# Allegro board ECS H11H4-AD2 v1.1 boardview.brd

Outline 200 x 243.84 mm; copper layers: TOP, PWR, GND, BOTTOM. Coordinates in mm from the lower left corner of the outline.
Outline path: 0,239.78 0,4.06 0,4.06 arc(1.19,1.19) 4.06,0 4.06,0 195.94,0 195.94,0 arc(198.81,1.19) 200,4.06 200,4.06 200,239.78 200,239.78 arc(198.81,242.65) 195.94,243.84 195.94,243.84 4.06,243.84 4.06,243.84 arc(1.19,242.65) 0,239.78 0,239.78

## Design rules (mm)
net group DIFFPAIR135: nets M_CLK_A_N1 M_CLK_A_P1
net group DIFFPAIR136: nets M_CLK_A_N0 M_CLK_A_P0
net group DIFFPAIR337: nets USB3_TX_N3 USB3_TX_P3
net group DIFFPAIR338: nets USB3_RX_N3_R USB3_RX_P3_R
net group DIFFPAIR339: nets USB3_TX_N3_R USB3_TX_P3_R
net group DIFFPAIR351: nets CPU_BCLK_N CPU_BCLK_P
net group DIFFPAIR353: nets CPU_24MCLK_N CPU_24MCLK_P
net group DIFFPAIR355: nets PEX1_RX_N5 PEX1_RX_P5
net group DIFFPAIR356: nets HSODN5 HSODP5
net group DIFFPAIR357: nets PEX1_TX_N5 PEX1_TX_P5
net group DIFFPAIR358: nets GLAN_CLKN GLAN_CLKP
net group DIFFPAIR359: nets GLAN_TX_C_N6 GLAN_TX_C_P6
net group DIFFPAIR360: nets GLAN_TX_N6 GLAN_TX_P6
net group DIFFPAIR361: nets GLAN_RX_C_N6 GLAN_RX_C_P6
net group DIFFPAIR362: nets GLAN_RX_N6 GLAN_RX_P6
net group DIFFPAIR363: nets PEX1_TX_N8 PEX1_TX_P8
net group DIFFPAIR366: nets PEX1_RX_N8 PEX1_RX_P8
net group DIFFPAIR380: nets USB10+ USB10-
net group DIFFPAIR381: nets USB_H1 USB_L1
net group DIFFPAIR382: nets USB_H2 USB_L2
net group DIFFPAIR419: nets USB3_TX_N3_C USB3_TX_P3_C
net group DIFFPAIR420: nets USB_N3_R USB_P3_R
net group DIFFPAIR421: nets USB_N4_R USB_P4_R
net group DIFFPAIR422: nets USB+7 USB-7
net group DIFFPAIR423: nets SSD_100M_N SSD_100M_P
net group DIFFPAIR429: nets SATA_PCIE_TXN_S SATA_PCIE_TXP_S
net group DIFFPAIR430: nets SATA_PCIE_RXN_S SATA_PCIE_RXP_S
net group DIFFPAIR436: nets VCORE_GSENS VCORE_SENS
net group DIFFPAIR439: nets VCORE_GT_GSENS VCORE_GT_SENS
net group DIFFPAIR448: nets USB3_TX_N2_C USB3_TX_P2_C
net group DIFFPAIR449: nets MPEX1_TX_N10 MPEX1_TX_P10
net group DIFFPAIR450: nets M_PEX1_TX_N10 M_PEX1_TX_P10
net group DIFFPAIR451: nets M_PEX1_RX_N10 M_PEX1_RX_P10
net group DIFFPAIR452: nets USB_N3 USB_P3
net group DIFFPAIR453: nets USB_N4 USB_P4
net group DIFFPAIR454: nets N24049344 VSUMA-
net group DIFFPAIR455: nets N24049550 VSUMB-
net group DIFFPAIR456: nets PEX1_TX_N7_S PEX1_TX_P7_S
net group DIFFPAIR457: nets PEX1_RX_N7_S PEX1_RX_P7_S
net group PCH-CLK: nets PEX16_100M_N PEX16_100M_P
net group VRD: nets VRD_THERMDA VRD_THERMDC
net group DDR_DQS_A: nets M_DQS_A_N0 M_DQS_A_N1 M_DQS_A_N2 M_DQS_A_N3 M_DQS_A_N4 M_DQS_A_N5 M_DQS_A_N6 M_DQS_A_N7 M_DQS_A_P0 M_DQS_A_P1 M_DQS_A_P2 M_DQS_A_P3 M_DQS_A_P4 M_DQS_A_P5 M_DQS_A_P6 M_DQS_A_P7
net group DDR_DQS_B: nets M_DQS_B_N0 M_DQS_B_N1 M_DQS_B_N2 M_DQS_B_N3 M_DQS_B_N4 M_DQS_B_N5 M_DQS_B_N6 M_DQS_B_N7 M_DQS_B_P0 M_DQS_B_P1 M_DQS_B_P2 M_DQS_B_P3 M_DQS_B_P4 M_DQS_B_P5 M_DQS_B_P6 M_DQS_B_P7
net group DDRCLK-B: nets M_CLK_B_N0 M_CLK_B_N1 M_CLK_B_P0 M_CLK_B_P1
net group DDRCMD-A: nets M_BS_A0 M_BS_A1 M_BS_A2 M_CAS_A_L M_MA_A0 M_MA_A1 M_MA_A2 M_MA_A3 M_MA_A4 M_MA_A5 M_MA_A6 M_MA_A7 M_MA_A8 M_MA_A9 M_MA_A10 M_MA_A11 M_MA_A12 M_MA_A13 M_MA_A14 M_MA_A15 M_RAS_A_L M_WE_A_L
net group DDRCMD-B: nets M_BS_B0 M_BS_B1 M_BS_B2 M_CAS_B_L M_MA_B0 M_MA_B1 M_MA_B2 M_MA_B3 M_MA_B4 M_MA_B5 M_MA_B6 M_MA_B7 M_MA_B8 M_MA_B9 M_MA_B10 M_MA_B11 M_MA_B12 M_MA_B13 M_MA_B14 M_MA_B15 M_RAS_B_L M_WE_B_L
net group DDRCTRL-A: nets M_CKE_A0 M_CKE_A1 M_CS_A_L0 M_CS_A_L1 M_ODT_A0 M_ODT_A1
net group DDRCTRL-B: nets M_CKE_B0 M_CKE_B1 M_CS_B_L0 M_CS_B_L1 M_ODT_B0 M_ODT_B1
net group DIFF-CLK: nets CPU_PCIBCLK_N PEX1_100M_N PEX1_100M_P WLAN_100M_N WLAN_100M_P
net group DIFFPAIR352: nets CPU_PCIBCLK_P
net group DIFFPAIR364: nets PEX1_TX_P7
net group DMI: nets DMI_RX_N0 DMI_RX_N1 DMI_RX_N2 DMI_RX_N3 DMI_RX_P0 DMI_RX_P1 DMI_RX_P2 DMI_RX_P3 DMI_TX_N0 DMI_TX_N1 DMI_TX_N2 DMI_TX_N3 DMI_TX_P0 DMI_TX_P1 DMI_TX_P2 DMI_TX_P3
net group DP: nets DDI3_AUX_N DDI3_AUX_P DDI3_TX_N0 DDI3_TX_N1 DDI3_TX_P0 DDI3_TX_P1 DPVGA_AUX_N DPVGA_AUX_P DPVGA_TX_N0 DPVGA_TX_N1 DPVGA_TX_P0 DPVGA_TX_P1
net group GND: nets GND
net group HDMI: nets DDI1_TX_N0 DDI1_TX_N1 DDI1_TX_N2 DDI1_TX_N3 DDI1_TX_P0 DDI1_TX_P1 DDI1_TX_P2 DDI1_TX_P3 DDI2_TX_N0 DDI2_TX_N1 DDI2_TX_N2 DDI2_TX_N3 DDI2_TX_P0 DDI2_TX_P1 DDI2_TX_P2 DDI2_TX_P3 HDMI0_CLK_N3 HDMI0_CLK_N3_R HDMI0_CLK_P3 HDMI0_CLK_P3_R HDMI0_TX_N0 HDMI0_TX_N0_R HDMI0_TX_N1 HDMI0_TX_N1_R HDMI0_TX_N2 HDMI0_TX_N2_R HDMI0_TX_P0 HDMI0_TX_P0_R HDMI0_TX_P1 HDMI0_TX_P1_R HDMI0_TX_P2 HDMI0_TX_P2_R HDMI_CLK_N3 HDMI_CLK_N3_R HDMI_CLK_P3 HDMI_CLK_P3_R HDMI_TX_N0 HDMI_TX_N0_R HDMI_TX_N1 HDMI_TX_N1_R HDMI_TX_N2 HDMI_TX_N2_R HDMI_TX_P0 HDMI_TX_P0_R HDMI_TX_P1 HDMI_TX_P1_R HDMI_TX_P2 HDMI_TX_P2_R
net group LAN: nets MDI0_N MDI0_P MDI1_N MDI1_P MDI2_N MDI2_P MDI3_N MDI3_P
net group M_DATA_A: nets M_DATA_A0 M_DATA_A1 M_DATA_A2 M_DATA_A3 M_DATA_A4 M_DATA_A5 M_DATA_A6 M_DATA_A7 M_DATA_A8 M_DATA_A9 M_DATA_A10 M_DATA_A11 M_DATA_A12 M_DATA_A13 M_DATA_A14 M_DATA_A15 M_DATA_A16 M_DATA_A17 M_DATA_A18 M_DATA_A19 M_DATA_A20 M_DATA_A21 M_DATA_A22 M_DATA_A23 M_DATA_A24 M_DATA_A25 M_DATA_A26 M_DATA_A27 M_DATA_A28 M_DATA_A29 M_DATA_A30 M_DATA_A31 M_DATA_A32 M_DATA_A33 M_DATA_A34 M_DATA_A35 M_DATA_A36 M_DATA_A37 M_DATA_A38 M_DATA_A39 M_DATA_A40 M_DATA_A41 M_DATA_A42 M_DATA_A43 M_DATA_A44 M_DATA_A45 M_DATA_A46 M_DATA_A47 M_DATA_A48 M_DATA_A49 M_DATA_A50 M_DATA_A51 M_DATA_A52 M_DATA_A53 M_DATA_A54 M_DATA_A55 M_DATA_A56 M_DATA_A57 M_DATA_A58 M_DATA_A59 M_DATA_A60 M_DATA_A61 M_DATA_A62 M_DATA_A63
net group M_DATA_B: nets M_DATA_B0 M_DATA_B1 M_DATA_B2 M_DATA_B3 M_DATA_B4 M_DATA_B5 M_DATA_B6 M_DATA_B7 M_DATA_B8 M_DATA_B9 M_DATA_B10 M_DATA_B11 M_DATA_B12 M_DATA_B13 M_DATA_B14 M_DATA_B15 M_DATA_B16 M_DATA_B17 M_DATA_B18 M_DATA_B19 M_DATA_B20 M_DATA_B21 M_DATA_B22 M_DATA_B23 M_DATA_B24 M_DATA_B25 M_DATA_B26 M_DATA_B27 M_DATA_B28 M_DATA_B29 M_DATA_B30 M_DATA_B31 M_DATA_B32 M_DATA_B33 M_DATA_B34 M_DATA_B35 M_DATA_B36 M_DATA_B37 M_DATA_B38 M_DATA_B39 M_DATA_B40 M_DATA_B41 M_DATA_B42 M_DATA_B43 M_DATA_B44 M_DATA_B45 M_DATA_B46 M_DATA_B47 M_DATA_B48 M_DATA_B49 M_DATA_B50 M_DATA_B51 M_DATA_B52 M_DATA_B53 M_DATA_B54 M_DATA_B55 M_DATA_B56 M_DATA_B57 M_DATA_B58 M_DATA_B59 M_DATA_B60 M_DATA_B61 M_DATA_B62 M_DATA_B63
net group PCH-PCIE: nets PEX1_RX_N7 PEX1_RX_P7 PEX1_TX_N7
net group PCIE-16X: nets PEG_RX_N0 PEG_RX_N1 PEG_RX_N2 PEG_RX_N3 PEG_RX_N4 PEG_RX_N5 PEG_RX_N6 PEG_RX_N7 PEG_RX_N8 PEG_RX_N9 PEG_RX_N10 PEG_RX_N11 PEG_RX_N12 PEG_RX_N13 PEG_RX_N14 PEG_RX_N15 PEG_RX_P0 PEG_RX_P1 PEG_RX_P2 PEG_RX_P3 PEG_RX_P4 PEG_RX_P5 PEG_RX_P6 PEG_RX_P7 PEG_RX_P8 PEG_RX_P9 PEG_RX_P10 PEG_RX_P11 PEG_RX_P12 PEG_RX_P13 PEG_RX_P14 PEG_RX_P15 PEG_TX_C_N0 PEG_TX_C_N1 PEG_TX_C_N2 PEG_TX_C_N3 PEG_TX_C_N4 PEG_TX_C_N5 PEG_TX_C_N6 PEG_TX_C_N7 PEG_TX_C_N8 PEG_TX_C_N9 PEG_TX_C_N10 PEG_TX_C_N11 PEG_TX_C_N12 PEG_TX_C_N13 PEG_TX_C_N14 PEG_TX_C_N15 PEG_TX_C_P0 PEG_TX_C_P1 PEG_TX_C_P2 PEG_TX_C_P3 PEG_TX_C_P4 PEG_TX_C_P5 PEG_TX_C_P6 PEG_TX_C_P7 PEG_TX_C_P8 PEG_TX_C_P9 PEG_TX_C_P10 PEG_TX_C_P11 PEG_TX_C_P12 PEG_TX_C_P13 PEG_TX_C_P14 PEG_TX_C_P15 PEG_TX_N0 PEG_TX_N1 PEG_TX_N2 PEG_TX_N3 PEG_TX_N4 PEG_TX_N5 PEG_TX_N6 PEG_TX_N7 PEG_TX_N8 PEG_TX_N9 PEG_TX_N10 PEG_TX_N11 PEG_TX_N12 PEG_TX_N13 PEG_TX_N14 PEG_TX_N15 PEG_TX_P0 PEG_TX_P1 PEG_TX_P2 PEG_TX_P3 PEG_TX_P4 PEG_TX_P5 PEG_TX_P6 PEG_TX_P7 PEG_TX_P8 PEG_TX_P9 PEG_TX_P10 PEG_TX_P11 PEG_TX_P12 PEG_TX_P13 PEG_TX_P14 PEG_TX_P15
net group RGB: nets VGA_BLUE VGA_GREEN VGA_RED
net group SATA30: nets SATA3_RX_N0 SATA3_RX_N2 SATA3_RX_N3 SATA3_RX_P0 SATA3_RX_P2 SATA3_RX_P3 SATA3_TX_N0 SATA3_TX_N2 SATA3_TX_N3 SATA3_TX_P0 SATA3_TX_P2 SATA3_TX_P3 SATA3R_N2 SATA3R_N3 SATA3R_P2 SATA3R_P3 SATA3T_N2 SATA3T_N3 SATA3T_P2 SATA3T_P3
net group SEN: nets AV1N AV2N AV3N BV1N BV2N PHASE1A_R PHASE1B_R PHASE2A_R PHASE2B_R PHASE3A_R
net group UG: nets AG1_PHASE_R AG2_PHASE_R AG3_PHASE_R BG2_PHASE_R BOOT2B_C BOOT3A_C UGATE1A_G UGATE1B_G UGATE2A_G UGATE2B_G UGATE3A_G
net group USB20: nets SMBDATA_STBY USB+5 USB+6 USB+8 USB+9 USB-5 USB-6 USB-8 USB-9 USB_N1 USB_N2 USB_N5 USB_N6 USB_N7 USB_N8 USB_N9 USB_N10 USB_P1 USB_P2 USB_P5 USB_P6 USB_P7 USB_P8 USB_P9 USB_P10
net group USB30: nets USB3_RX_N1 USB3_RX_N1_R USB3_RX_N2 USB3_RX_N2_R USB3_RX_N3 USB3_RX_N4 USB3_RX_N4_R USB3_RX_P1 USB3_RX_P1_R USB3_RX_P2 USB3_RX_P2_R USB3_RX_P3 USB3_RX_P4 USB3_RX_P4_R USB3_TX_N1 USB3_TX_N1_C USB3_TX_N1_R USB3_TX_N2 USB3_TX_N2_R USB3_TX_N4 USB3_TX_N4_C USB3_TX_N4_R USB3_TX_P1 USB3_TX_P1_C USB3_TX_P1_R USB3_TX_P2 USB3_TX_P2_R USB3_TX_P4 USB3_TX_P4_C USB3_TX_P4_R

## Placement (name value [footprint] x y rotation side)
A1  h2x1-wh  [J2X1]  84.68 34.67 270 top
A2  h2x1-wh  [J2X1]  87.86 34.67 270 top
ATX_12V  pw-4p2r  [ATX_PWR_4P_2]  191.56 195.64 180 top
ATX_POWER  atx-pw-24p2r  [ATX_PWR_24P_1]  153.26 37.85 270 top
AUDIO  au-13p-bl+li+pk  [AUDIO_JACK_13P-COLAY_2]  52.09 235.26 0 top
BAT1  sk-cr2032-d  [BATTERY_HOLDER_CR2032-LOTES]  60.17 154.94 0 top
BOSS1  boss_m2_h1.45  [HOLE_TC256BC180D165PT]  37.19 146.72 270 top
BOSS2  boss_m2_h1.45-o  [HOLE_TC256BC180D165PT]  145 14.17 0 top
BOSS3  boss_m2_h1.45  [HOLE_TC256BC180D165PT]  183 14.17 0 top
BT1  bat54a-s  [BAT54_132_2]  50.01 188.85 270 top
BT2  bat54a-s-o  [BAT54_132_2]  28.42 94.62 0 top
BT3  bat54a-s  [BAT54_132_2]  194.03 50.55 90 top
BZ  buzzer-d  [BUZZER_1]  190.47 37.47 180 top
C1  .1u-16vx7-04-o  [C0402_2]  166.09 233.81 270 top
C2  10u-6v3x5-06-o  [C0603_4D7UF]  192.2 233.53 90 top
C3  .1u-25vx7-06-o  [C0603_2]  164.87 233.43 90 top
C4  4.7u-6v3x5-06-o  [C0603_4D7UF]  185.89 233.43 90 top
C5  .1u-16vx7-04-o  [C0402_2]  187.17 233.05 90 top
C6  10u-6v3x5-06-o  [C0603_4D7UF]  194.03 230.95 0 top
C7  3.3p-04-o  [C0402_2]  173 230.84 270 top
C8  3.3p-04-o  [C0402_2]  169.39 230.81 270 top
C9  3.3p-04-o  [C0402_2]  177.57 230.2 270 top
C10  3.3p-04-o  [C0402_2]  179.76 230.2 90 top
C11  4.7u-6v3x5-06-o  [C0603_4D7UF]  183.36 229.93 180 top
C12  470p-50vx7-04-o  [C0402_2]  128.37 229.62 0 top
C13  .1u-16vx7-04-o  [C0402_2]  193.83 229.16 270 top
C14  1u-6v3x5-04-o  [C0402_2]  194.92 229.16 270 top
C15  .1u-16vx7-04-o  [C0402_2]  183.62 228.68 180 top
C16  1000p-50vx7-04  [C0402_2]  133.07 228.47 90 top
C17  10u-6v3x5-08  [C0805_2]  23.34 227.97 0 top
C18  1000p-50vx7-04  [C0402_2]  153.09 227.91 270 top
C19  1u-6v3x5-04  [C0402_2]  154.15 227.91 270 top
C20  .1u-16vx7-04-o  [C0402_2]  183.62 227.61 180 top
C21  3.3p-04-o  [C0402_2]  177.57 227.66 270 top
C22  3.3p-04-o  [C0402_2]  179.76 227.66 90 top
C23  10u-6v3x5-08  [C0805_2]  16.48 226.44 90 top
C24  10u-6v3x5-08  [C0805_2]  20.68 226.44 90 top
C25  .1u-16vy5-04-o  [C0402_2]  18.01 225.81 90 top
C26  .1u-16vx7-04  [C0402_2]  22.71 225.35 0 top
C27  10u-6v3x5-08  [C0805_2]  25.88 225.3 180 top
C28  3.3p-04-o  [C0402_2]  177.57 225.22 270 top
C29  3.3p-04-o  [C0402_2]  179.76 225.22 90 top
C30  .1u-25vx5-04  [C0402_2]  158.14 225.45 90 top
C31  470p-50vx7-04-o  [C0402_2]  128.37 225.04 0 top
C32  100p-04  [C0402_2]  42.65 224.79 180 top
C33  1u-6v3x5-04-o  [C0402_2]  183.62 224.66 180 top
C34  .1u-16vx7-04-o  [C0402_2]  193.52 224.69 0 top
C35  .1u-16vx7-04  [C0402_2]  110.26 224.21 270 top
C36  .1u-16vy5-04-o  [C0402_2]  88.75 224.03 270 top
C37  1200p-50vx7-04  [C0402_2]  164.95 224.03 270 top
C38  330p-50vx7-04  [C0402_2]  168.38 224.03 270 top
C39  .22u-25vx7-06  [C0603_2]  170.71 224.03 270 top
C40  .33u-10vx7-06  [C0603_2]  172.03 224.03 270 top
C41  .1u-16vx7-04-o  [C0402_2]  185.88 223.62 270 top
C42  1000p-50vx7-04-o  [C0402_2]  154.91 223.6 0 top
C43  .1u-16vx7-04-o  [C0402_2]  191.82 223.49 270 top
C44  10u-6v3x5-08  [C0805_2]  25.88 223.27 180 top
C45  .1u-16vx7-04-o  [C0402_2]  183.06 223.01 270 top
C46  470p-50vx7-04-o  [C0402_2]  145.96 223.72 180 top
C47  470p-50vx7-04-o  [C0402_2]  152.44 222.83 180 top
C48  100p-04  [C0402_2]  39.22 222 90 top
C49  330p-50vx7-04  [C0402_2]  167.16 221.89 90 top
C50  10u-6v3x5-08  [C0805_2]  10.88 221.8 180 top
C51  1u-6v3x5-04  [C0402_2]  64.87 221.74 180 top
C52  2200p-50vx7-04  [C0402_2]  169.01 221.49 270 top
C53  .1u-16vx7-04  [C0402_2]  170.43 221.49 90 top
C54  10u-6v3x5-08  [C0805_2]  25.88 221.23 180 top
C55  .1u-16vy5-04  [C0402_2]  65.33 220.17 90 top
C56  .1u-16vx7-04  [C0402_2]  116.56 220.47 90 top
C57  .1u-16vx7-04  [C0402_2]  117.7 220.47 90 top
C58  .1u-16vx7-04  [C0402_2]  118.85 220.47 90 top
C59  .1u-16vx7-04  [C0402_2]  119.99 220.47 90 top
C60  .1u-16vx7-04  [C0402_2]  121.13 220.47 90 top
C61  .1u-16vx7-04  [C0402_2]  122.28 220.47 90 top
C62  .1u-16vx7-04  [C0402_2]  123.42 220.47 90 top
C63  .1u-16vx7-04  [C0402_2]  124.56 220.47 90 top
C64  .1u-16vx7-04  [C0402_2]  11.53 220.27 180 top
C65  100p-04  [C0402_2]  58.78 220.27 270 top
C66  100p-04  [C0402_2]  50.29 220.24 270 top
C67  100p-04  [C0402_2]  54.31 220.24 270 top
C68  100p-04  [C0402_2]  45.82 220.09 270 top
C69  10u-6v3x5-08  [C0805_2]  25.88 219.2 180 top
C70  .022u-16vx7-04  [C0402_2]  173.2 219.13 270 top
C71  220p-50vx7-04  [C0402_2]  166 218.95 270 top
C72  3300p-50vx7-04  [C0402_2]  163.8 218.95 90 top
C73  68p-04  [C0402_2]  164.87 218.95 90 top
C74  .022u-16vx7-04  [C0402_2]  179.04 218.95 90 top
C75  .1u-16vx7-04  [C0402_2]  134.34 217.65 90 top
C76  .1u-16vx7-04  [C0402_2]  135.48 217.65 90 top
C77  10p-04  [C0402_2]  112.5 225.17 90 top
C78  .1u-16vx7-04  [C0402_2]  136.63 217.65 90 top
C79  .1u-16vx7-04  [C0402_2]  137.77 217.65 90 top
C80  .1u-16vx7-04  [C0402_2]  138.91 217.65 90 top
C81  .1u-16vx7-04  [C0402_2]  140.06 217.65 90 top
C82  .1u-16vx7-04  [C0402_2]  141.2 217.65 90 top
C83  .1u-16vx7-04  [C0402_2]  142.34 217.65 90 top
C84  4.7u-25vx5-08  [C0805_2]  25.88 217.17 0 top
C85  1000p-50vx7-04  [C0402_2]  166 216.87 270 top
C86  10p-04  [C0402_2]  112.5 227.84 270 top
C87  10p-04  [C0402_2]  150.79 222.38 90 top
C88  .1u-16vx7-04  [C0402_2]  95.48 216.41 90 top
C89  .1u-16vx7-04  [C0402_2]  96.6 216.41 90 top
C90  .1u-16vx7-04  [C0402_2]  97.66 216.41 90 top
C91  .1u-16vx7-04  [C0402_2]  98.78 216.41 90 top
C92  .1u-25vx5-04  [C0402_2]  162.66 216.41 270 top
C93  .1u-16vy5-04  [C0402_2]  101.37 212.32 270 top
C94  330p-50vx7-04  [C0402_2]  172.34 215.27 0 top
C95  10p-04  [C0402_2]  147.55 222.38 90 top
C96  4.7u-25vx5-08  [C0805_2]  25.88 215.14 0 top
C97  .1u-16vy5-04  [C0402_2]  83.67 214.63 90 top
C100  22u-6v3x5-08  [C0805_2]  42.14 214.25 270 top
C101  .1u-25vx5-04-o  [C0402_2]  119.1 214.12 270 top
C104  .22u-16vx7-04  [C0402_2]  158.34 214 0 top
C105  470p-50vx7-04  [C0402_2]  79.98 213.87 270 top
C109  .022u-16vx7-04  [C0402_2]  181.33 213.87 90 top
C110  .1u-16vy5-04  [C0402_2]  110.11 212.55 90 top
C117  .1u-16vy5-04  [C0402_2]  73.1 213.64 90 top
C118  470p-50vx7-04  [C0402_2]  63.73 213.61 90 top
C119  470p-50vx7-04  [C0402_2]  67.64 213.61 90 top
C120  .1u-16vy5-04  [C0402_2]  68.73 213.61 90 top
C121  470p-50vx7-04-o  [C0402_2]  112.12 213.77 270 top
C122  .1u-16vy5-04  [C0402_2]  86 213.16 0 top
C123  4700p-25vx7-04  [C0402_2]  172.44 212.85 180 top
C124  100p-04  [C0402_2]  9.63 212.72 180 top
C125  .22u-16vx7-04  [C0402_2]  158.34 212.09 0 top
C126  .1u-16vx7-04  [C0402_2]  101.8 216.97 90 top
C127  1u-6v3x5-04-o  [C0402_2]  170.48 210.79 0 top
C128  .1u-16vx7-04  [C0402_2]  14.2 210.57 270 top
C129  22p-04-o  [C0402_2]  18.9 210.57 270 top
C130  .1u-16vy5-04-o  [C0402_2]  21.18 210.57 270 top
C131  .1u-16vy5-04-o  [C0402_2]  22.33 210.57 270 top
C132  10u-10vy5-08  [C0805_2]  16 209.91 270 top
C133  1u-25vx5-06  [C0603_2]  154.66 209.68 0 top
C136  680p-50vx7-04  [C0402_2]  125.6 209.47 180 top
C137  .22u-16vx7-04  [C0402_2]  158.34 209.17 0 top
C138  100p-04  [C0402_2]  9.75 208.15 180 top
C139  2.7p-04  [C0402_2]  68.17 207.77 270 top
C140  2.7p-04  [C0402_2]  69.44 207.77 270 top
C141  2.7p-04  [C0402_2]  70.59 207.77 270 top
C142  2.7p-04  [C0402_2]  71.86 207.77 270 top
C143  2.7p-04  [C0402_2]  73 207.77 270 top
C144  2.7p-04  [C0402_2]  74.27 207.77 270 top
C145  2.7p-04  [C0402_2]  75.41 207.77 270 top
C146  2.7p-04  [C0402_2]  76.68 207.77 270 top
C147  1u-16vx5-04  [C0402_2]  113.77 207.52 180 top
C148  .1u-16vx7-04  [C0402_2]  121.64 207.52 180 top
C149  330p-50vx7-04  [C0402_2]  174.98 207.14 0 top
C150  10u-16vx5-08  [C0805_2]  128.37 206.76 270 top
C151  1u-16vx5-04  [C0402_2]  129.9 206.76 270 top
C152  1u-16vx5-04  [C0402_2]  138.15 206.76 270 top
C153  10u-16vx5-08  [C0805_2]  139.67 206.76 270 top
C154  470p-50vx7-04  [C0402_2]  9.75 206.63 180 top
C155  .1u-16vx7-04  [C0402_2]  48.62 205.74 270 top
C156  .1u-16vx7-04  [C0402_2]  52.93 205.74 270 top
C157  10u-10vy5-08  [C0805_2]  14.96 205.61 270 top
C158  .1u-25vx5-04  [C0402_2]  161.52 204.98 0 top
C166  2200p-50vx7-04  [C0402_2]  166.6 204.98 270 top
C167  .022u-16vx7-04  [C0402_2]  169.47 204.98 270 top
C168  .022u-16vx7-04  [C0402_2]  173.2 204.98 90 top
C169  10u-16vx5-08  [C0805_2]  103.73 204.34 90 top
C170  68p-04  [C0402_2]  163.17 204.22 90 top
C171  1000p-50vx7-04  [C0402_2]  165.46 204.22 90 top
C172  .1u-16vx7-04  [C0402_2]  56.62 203.58 0 top
C173  .1u-16vx7-04  [C0402_2]  94.84 203.58 180 top
C174  .22u-16vx7-04  [C0402_2]  171.63 203.53 270 top
C175  560p-50vx7-04  [C0402_2]  158.98 203.33 0 top
C176  .1u-16vx7-04  [C0402_2]  120.62 202.56 270 top
C177  .1u-16vx7-04  [C0402_2]  56.62 202.31 180 top
C178  .22u-16vx5-04  [C0402_2]  167.11 202.18 0 top
C179  .1u-16vx7-04  [C0402_2]  46.46 202.06 180 top
C180  .01u-25vx7-04-o  [C0402_2]  91.92 201.93 90 top
C181  1800p-50vx7-04  [C0402_2]  164.24 201.7 90 top
C182  .1u-25vx5-04  [C0402_2]  184.51 201.3 270 top
C183  1u-16vx5-04  [C0402_2]  185.65 201.3 270 top
C184  220p-50vx7-04  [C0402_2]  161.52 201.04 180 top
C185  .1u-16vx7-04  [C0402_2]  22.96 200.03 90 top
C186  .1u-16vx7-04  [C0402_2]  75.54 200.03 0 top
C187  680p-50vx7-04  [C0402_2]  158.98 199.9 0 top
C188  330p-50vx7-04  [C0402_2]  163.61 199.9 0 top
C189  330p-50vx7-04  [C0402_2]  165.71 199.9 180 top
C193  1u-16vx5-04  [C0402_2]  167.81 199.9 0 top
C195  .1u-16vx7-04  [C0402_2]  33.25 199.77 90 top
C196  .1u-16vx7-04  [C0402_2]  46.71 199.77 0 top
C197  1500p-50vx7-04  [C0402_2]  100.69 199.52 90 top
C198  .1u-16vx7-04  [C0402_2]  46.71 198.63 0 top
C199  100p-04  [C0402_2]  3.88 197.49 90 top
C200  100p-04  [C0402_2]  8.36 197.49 90 top
C201  27p-04  [C0402_2]  61.44 197.49 90 top
C202  .1u-16vx7-04  [C0402_2]  22.96 196.34 270 top
C203  .1u-16vx7-04  [C0402_2]  53.7 196.34 0 top
C204  .1u-16vx7-04  [C0402_2]  33.25 196.22 270 top
C205  .1u-16vx7-04  [C0402_2]  45.69 195.91 90 top
C206  .1u-16vx7-04  [C0402_2]  46.84 195.91 90 top
C207  .1u-16vx7-04  [C0402_2]  51.33 195.91 270 top
C208  4.7u-6v3x5-06  [C0603_4D7UF]  53.7 195.07 0 top
C209  27p-04  [C0402_2]  61.44 194.56 270 top
C210  1u-16vx5-04  [C0402_2]  94.46 194.44 90 top
C211  .22u-16vx7-04  [C0402_2]  95.61 194.44 270 top
C212  .1u-16vx7-04  [C0402_2]  55.88 192.28 90 top
C213  .1u-16vx7-04-o  [C0402_2]  56.95 192.28 90 top
C214  1u-10vy5-06-o  [C0603_2]  58.14 192.28 270 top
C215  4.7u-6v3x5-06  [C0603_4D7UF]  59.54 192.28 90 top
C216  .1u-16vx7-04  [C0402_2]  22.2 191.26 90 top
C217  .1u-16vx7-04  [C0402_2]  23.34 191.26 90 top
C218  10p-04-o  [C0402_2]  49.12 191.26 0 top
C219  .1u-16vx7-04  [C0402_2]  33.38 190.25 270 top
C220  1500p-50vx7-04  [C0402_2]  114.15 190.25 90 top
C221  1500p-50vx7-04  [C0402_2]  131.93 190.25 90 top
C222  .1u-16vx7-04  [C0402_2]  185.52 189.61 270 top
C223  10u-16vx5-08-o  [C0805_2]  172.06 189.48 270 top
C224  10u-16vx5-08-o  [C0805_2]  174.09 189.48 270 top
C225  .1u-16vx7-04  [C0402_2]  42.49 188.65 270 top
C226  .1u-16vx7-04  [C0402_2]  33.38 188.15 90 top
C227  .1u-16vx7-04  [C0402_2]  11.53 188.09 90 top
C228  .1u-16vx7-04-o  [C0402_2]  52.55 187.83 90 top
C229  10p-04-o  [C0402_2]  42.52 186.31 90 top
C230  10p-04-o  [C0402_2]  22.2 186.06 270 top
C231  10u-6v3x5-06  [C0603_4D7UF]  33.12 185.61 270 top
C232  10u-6v3x5-06  [C0603_4D7UF]  11.4 184.4 270 top
C233  .1u-16vx7-04-o  [C0402_2]  50.52 183.95 270 top
C234  10u-16vx5-08-o  [C0805_2]  179.04 183.26 90 top
C235  .22u-16vx5-04  [C0402_2]  22.83 182.75 180 top
C236  .1u-16vx7-04  [C0402_2]  43.92 182.37 180 top
C237  .22u-16vx5-04  [C0402_2]  22.83 181.48 180 top
C238  .1u-16vx7-04  [C0402_2]  43.92 181.23 180 top
C239  1500p-50vx7-04  [C0402_2]  179.17 180.97 0 top
C240  .1u-25vx5-04  [C0402_2]  190.47 180.34 270 top
C241  .22u-16vx5-04  [C0402_2]  22.83 179.58 180 top
C242  .22u-16vx5-04  [C0402_2]  22.83 178.31 180 top
C243  .22u-16vx7-04  [C0402_2]  187.93 178.18 270 top
C244  1u-16vx5-04  [C0402_2]  192.38 176.53 0 top
C245  .22u-16vx5-04  [C0402_2]  22.83 175.01 180 top
C246  10u-16vx5-08  [C0805_2]  192.38 175.01 0 top
C247  22u-6v3x5  [C0603_4D7UF]  121.89 174.5 180 top
C248  22u-6v3x5  [C0603_4D7UF]  124.88 174.5 0 top
C249  22u-6v3x5  [C0603_4D7UF]  127.8 174.5 0 top
C250  22u-6v3x5  [C0603_4D7UF]  130.73 174.5 0 top
C251  22u-6v3x5  [C0603_4D7UF]  133.69 174.5 0 top
C252  22u-6v3x5  [C0603_4D7UF]  136.65 174.5 180 top
C253  22u-6v3x5  [C0603_4D7UF]  139.65 174.5 180 top
C254  22u-6v3x5  [C0603_4D7UF]  142.62 174.5 0 top
C255  .22u-16vx5-04  [C0402_2]  22.83 173.86 180 top
C256  100p-04-o  [C0402_2]  66.9 173.36 180 top
C257  100p-04-o  [C0402_2]  73.51 172.21 180 top
C258  .22u-16vx5-04  [C0402_2]  22.83 170.94 180 top
C259  .22u-16vx5-04  [C0402_2]  22.83 169.8 180 top
C260  .22u-16vx5-04  [C0402_2]  22.83 166.88 180 top
C261  10u-16vx5-08  [C0805_2]  191.87 166.88 0 top
C262  .22u-16vx5-04  [C0402_2]  22.83 165.74 180 top
C263  22u-6v3x5-o  [C0603_4D7UF]  161.68 163.45 90 top
C264  22u-6v3x5-o  [C0603_4D7UF]  163.11 163.45 90 top
C265  1500p-50vx7-04  [C0402_2]  179.3 163.07 0 top
C266  .22u-16vx5-04  [C0402_2]  22.83 162.94 180 top
C267  10u-6v3x5-08-o  [C0805_2]  6.96 162.43 90 top
C268  10u-6v3x5-08-o  [C0805_2]  9.63 162.43 90 top
C269  220p-04-o  [C0402_2]  5.44 161.8 270 top
C270  .22u-16vx5-04  [C0402_2]  22.83 161.67 180 top
C271  22u-6v3x5-o  [C0603_4D7UF]  161.68 160.27 90 top
C272  22u-6v3x5-o  [C0603_4D7UF]  163.11 160.27 90 top
C273  10u-6v3x5-08-o  [C0805_2]  9.63 158.88 270 top
C274  .22u-16vx5-04  [C0402_2]  22.71 158.37 225 top
C275  .22u-16vx5-04  [C0402_2]  23.6 157.61 225 top
C276  47u-6v3x5-08-o  [C0805_2]  162.03 157.1 270 top
C277  10u-6v3x5-08-o  [C0805_2]  9.63 154.81 90 top
C278  .22u-16vx5-04  [C0402_2]  22.71 154.56 225 top
C279  .22u-16vx5-04  [C0402_2]  23.6 153.8 225 top
C280  47u-6v3x5-08-o  [C0805_2]  162.03 153.67 90 top
C281  22u-6v3x5-08  [C0805_2]  119.66 152.43 180 top
C282  47u-6v3x5-08  [C0805_2]  131.37 152.43 180 top
C283  22u-6v3x5-08  [C0805_2]  123.32 152.4 0 top
C284  .1u-16vy5-04  [C0402_2]  9.88 152.15 180 top
C285  22u-6v3x5  [C0603_4D7UF]  127.81 152.67 180 top
C286  1u-10vy5-06-o  [C0603_2]  8.1 151.26 270 top
C287  10u-6v3x5-08-o  [C0805_2]  6.45 151 270 top
C288  .1u-16vy5-04-o  [C0402_2]  9.88 151 0 top
C289  10u-6v3x5-06  [C0603_4D7UF]  72.49 150.71 0 top
C290  22u-6v3x5  [C0603_4D7UF]  115.75 150.65 0 top
C291  .22u-16vx5-04  [C0402_2]  22.71 150.62 225 top
C292  22u-6v3x5-08  [C0805_2]  119.66 150.5 180 top
C293  22u-6v3x5-08  [C0805_2]  123.32 150.47 0 top
C294  22u-6v3x5-08  [C0805_2]  127.69 150.98 0 top
C295  47u-6v3x5-08  [C0805_2]  131.37 150.47 180 top
C296  47u-6v3x5-08-o  [C0805_2]  162.03 150.24 270 top
C297  .22u-16vx5-04  [C0402_2]  23.47 149.73 225 top
C298  22u-6v3x5  [C0603_4D7UF]  115.75 149.26 0 top
C299  .1u-16vx7-04  [C0402_2]  71.22 149.23 0 top
C300  1u-25vx7-08  [C0805_2]  193.9 148.97 0 top
C303  22u-6v3x5-08  [C0805_2]  127.69 149.02 0 top
C304  47u-6v3x5-08  [C0805_2]  131.37 148.51 180 top
C305  1u-6v3x5-04  [C0402_2]  74.14 148.21 0 top
C306  22u-6v3x5  [C0603_4D7UF]  115.75 147.88 0 top
C307  .22u-16vx5-04  [C0402_2]  22.71 147.19 225 top
C309  .1u-16vx7-04-o  [C0402_2]  69.57 146.94 90 top
C310  22u-6v3x5  [C0603_4D7UF]  115.75 146.49 0 top
C311  47u-6v3x5-08-o  [C0805_2]  162.03 146.69 270 top
C314  22u-6v3x5-08  [C0805_2]  127.69 146.58 0 top
C315  47u-6v3x5-08  [C0805_2]  131.37 146.58 180 top
C316  .22u-16vx5-04  [C0402_2]  23.6 146.43 225 top
C317  1500p-50vx7-04  [C0402_2]  179.3 145.54 0 top
C318  .1u-16vx7-04-o  [C0402_2]  72.54 145.39 270 top
C319  22u-6v3x5-08  [C0805_2]  115.98 144.81 0 top
C320  .1u-25vx5-04  [C0402_2]  191.87 144.91 270 top
C321  1u-6v3x5-04  [C0402_2]  70.71 144.78 270 top
C322  22u-6v3x5-08  [C0805_2]  119.66 144.68 180 top
C323  22u-6v3x5-08  [C0805_2]  123.32 144.65 0 top
C324  22u-6v3x5-08  [C0805_2]  127.69 144.65 0 top
C325  47u-6v3x5-08  [C0805_2]  131.37 144.65 180 top
C326  22u-6v3x5  [C0603_4D7UF]  116.28 143.09 180 top
C327  22u-6v3x5-08  [C0805_2]  119.66 142.75 180 top
C328  .22u-16vx7-04  [C0402_2]  189.33 142.75 270 top
C329  22u-6v3x5-08  [C0805_2]  123.32 142.72 0 top
C330  22u-6v3x5-08  [C0805_2]  127.69 142.72 0 top
C331  47u-6v3x5-08  [C0805_2]  131.37 142.72 180 top
C332  .22u-16vx5-04  [C0402_2]  22.71 142.62 225 top
C333  .22u-16vx5-04  [C0402_2]  23.6 141.86 225 top
C334  .22u-16vx5-04  [C0402_2]  22.71 138.94 225 top
C335  .22u-16vx5-04  [C0402_2]  23.6 138.18 225 top
C336  22u-6v3x5  [C0603_4D7UF]  66.9 136.78 270 top
C337  22u-6v3x5  [C0603_4D7UF]  68.35 136.78 270 top
C338  22u-6v3x5  [C0603_4D7UF]  69.8 136.78 270 top
C339  22u-6v3x5-o  [C0603_4D7UF]  71.25 136.78 270 top
C340  .1u-16vx7-04  [C0402_2]  65.63 136.53 270 top
C341  10u-16vx5-08  [C0805_2]  195.22 135.38 180 top
C342  .22u-16vx5-04  [C0402_2]  22.71 134.75 225 top
C343  .22u-16vx5-04  [C0402_2]  23.47 133.86 225 top
C344  22u-6v3x5-o  [C0603_4D7UF]  73 133.73 180 top
C345  1u-25vx7-08  [C0805_2]  195.22 133.43 180 top
C346  .1u-16vx7-04-o  [C0402_2]  8.99 133.38 270 top
C347  .22u-16vx5-04  [C0402_2]  22.71 130.81 225 top
C348  .22u-16vx5-04  [C0402_2]  23.6 130.05 225 top
C349  .1u-16vx7-04-o  [C0402_2]  57.51 127.25 270 top
C350  2.2u-16vx5-06-o  [C0603_2]  3.81 127.13 270 top
C351  .22u-16vx5-04  [C0402_2]  22.71 127 225 top
C352  220p-04-o  [C0402_2]  65.38 126.97 0 top
C353  .22u-16vx5-04  [C0402_2]  59.08 126.34 180 top
C354  .22u-16vx5-04  [C0402_2]  23.57 126.14 225 top
C355  .1u-16vx7-04-o  [C0402_2]  66.22 124.33 180 top
C356  1u-6v3x5-04  [C0402_2]  58.78 123.7 180 top
C357  .22u-16vx5-04  [C0402_2]  22.71 122.94 225 top
C358  10u-6v3x5-06-o  [C0603_4D7UF]  51.54 122.94 90 top
C359  .1u-16vx7-04-o  [C0402_2]  50.01 122.56 90 top
C360  .1u-16vx7-04-o  [C0402_2]  52.86 122.56 90 top
C361  .1u-16vx7-04-o  [C0402_2]  53.95 122.56 90 top
C362  .22u-16vx5-04  [C0402_2]  23.6 122.17 225 top
C363  .1u-16vy5-04-o  [C0402_2]  182.55 121.06 270 top
C364  .1u-16vy5-04-o  [C0402_2]  187.5 121.01 90 top
C367  .1u-16vx-04-o  [C0402_2]  58.9 120.52 0 top
C368  10u-16vx5-08  [C0805_2]  62.81 120.42 180 top
C370  .1u-16vx7-04  [C0402_2]  60.53 119.25 270 top
C371  10u-16vx5-08  [C0805_2]  62.81 118.47 180 top
C379  .1u-16vx7-04  [C0402_2]  57 116.41 270 top
C380  10u-16vx5-08-o  [C0805_2]  60.43 115.7 90 top
C381  1u-10vy5-06-o  [C0603_2]  193.52 114.3 270 top
C382  .1u-16vx7-04  [C0402_2]  50.39 112.4 270 top
C383  .01u-25vx7-04  [C0402_2]  51.54 112.4 270 top
C384  10u-6v3x5-06  [C0603_4D7UF]  52.81 112.01 270 top
C385  22u-6v3x5-o  [C0603_4D7UF]  54.27 112.01 270 top
C386  22u-6v3x5-o  [C0603_4D7UF]  55.73 112.01 270 top
C387  .1u-16vx7-04  [C0402_2]  37.19 110.24 270 top
C388  .1u-16vx7-04  [C0402_2]  38.33 110.24 270 top
C389  .1u-16vy5-04-o  [C0402_2]  188.95 104.14 270 top
C390  4.7u-6v3x5-06  [C0603_4D7UF]  56.69 101.22 90 top
C391  .1u-16vx7-04  [C0402_2]  122.05 100.81 90 top
C392  .1u-16vx7-04  [C0402_2]  116.38 100.58 90 top
C393  .1u-16vx7-04  [C0402_2]  115.2 100.53 90 top
C394  10p-04-o  [C0402_2]  50.39 100.46 270 top
C395  10p-04-o  [C0402_2]  52.68 100.46 270 top
C396  10p-04-o  [C0402_2]  27.15 98.17 90 top
C397  10u-6v3x5-06  [C0603_4D7UF]  113.13 89.85 0 top
C398  22u-6v3x5-08  [C0805_2]  169.77 90.42 180 top
C399  .1u-25vx7-06  [C0603_2]  173.2 90.42 180 top
C400  10u-6v3x5-06  [C0603_4D7UF]  176.25 90.42 0 top
C401  .1u-16vx7-04  [C0402_2]  166.37 90.35 270 top
C402  1u-6v3x5-04  [C0402_2]  96.88 90.3 270 top
C403  1u-6v3x5-04  [C0402_2]  98.91 90.3 270 top
C404  1u-6v3x5-04  [C0402_2]  100.3 90.3 270 top
C405  1u-6v3x5-04  [C0402_2]  101.7 90.3 270 top
C406  1u-6v3x5-04  [C0402_2]  103.1 90.3 270 top
C407  .1u-16vx7-04  [C0402_2]  104.5 90.3 270 top
C408  .1u-16vx7-04  [C0402_2]  115.16 90.3 270 top
C409  .1u-16vx7-04  [C0402_2]  116.81 90.3 270 top
C410  .1u-16vx7-04  [C0402_2]  117.96 90.3 270 top
C411  .1u-16vx7-04  [C0402_2]  119.1 90.3 270 top
C412  .1u-16vx7-04  [C0402_2]  123.93 90.3 270 top
C413  .1u-16vx7-04  [C0402_2]  125.45 90.3 270 top
C414  .1u-16vx7-04  [C0402_2]  162.66 90.3 90 top
C415  4.7u-6v3x5-06  [C0603_4D7UF]  53.49 90.27 180 top
C416  1u-6v3x5-04  [C0402_2]  95.73 90.27 270 top
C417  .1u-16vx7-04  [C0402_2]  50.32 90.25 270 top
C418  .1u-16vx7-04  [C0402_2]  51.43 90.25 270 top
C419  .022u-16vx7-04  [C0402_2]  181.36 90.22 270 top
C420  1u-6v3x5-04  [C0402_2]  102.97 80.26 180 top
C421  .1u-16vx7-04  [C0402_2]  105.13 80.26 180 top
C422  1u-6v3x5-04  [C0402_2]  97.84 80.24 180 top
C423  .1u-16vx7-04  [C0402_2]  99.92 80.24 0 top
C424  .1u-16vx7-04  [C0402_2]  57.61 80.14 90 top
C425  .1u-16vx7-04  [C0402_2]  58.67 80.14 90 top
C426  .022u-16vx7-04  [C0402_2]  111.86 80.65 0 top
C427  .1u-16vx7-04  [C0402_2]  169.24 79.83 270 top
C428  22u-6v3x5-08  [C0805_2]  109.96 90.42 180 top
C429  .1u-16vx7-04  [C0402_2]  172.64 79.83 90 top
C430  .022u-16vx7-04  [C0402_2]  180.9 79.83 270 top
C432  22u-6v3x5  [C0603_4D7UF]  114.77 79.51 270 top
C433  22u-6v3x5  [C0603_4D7UF]  116.18 79.51 270 top
C434  22u-6v3x5  [C0603_4D7UF]  117.59 79.51 270 top
C435  22u-6v3x5  [C0603_4D7UF]  119 79.51 270 top
C436  22u-6v3x5  [C0603_4D7UF]  120.47 79.51 90 top
C437  .1u-25vx7-06  [C0603_2]  121.88 79.51 90 top
C438  22u-6v3x5-08  [C0805_2]  175.23 79.38 270 top
C439  10u-6v3x5-06  [C0603_4D7UF]  176.96 79.45 270 top
C440  .1u-25vx7-06  [C0603_2]  178.36 79.45 270 top
C441  22u-6v3x5  [C0603_4D7UF]  124.09 79.43 0 top
C442  .1u-16vx7-04  [C0402_2]  5.82 78.99 90 top
C443  22u-6v3x5  [C0603_4D7UF]  124.09 77.95 0 top
C444  .01u-25vx7-04  [C0402_2]  145.26 77.85 90 top
C445  1u-16vx5-04  [C0402_2]  146.41 77.85 270 top
C446  22u-6v3x5  [C0603_4D7UF]  124.09 76.48 0 top
C447  1000p-50vx7-04  [C0402_2]  139.04 76.58 270 top
C448  .1u-16vx-04-o  [C0402_2]  149.07 74.42 180 top
C449  .1u-16vx-04-o  [C0402_2]  149.07 73.28 180 top
C452  .01u-25vx7-04  [C0402_2]  92.43 71.91 180 top
C453  .01u-25vx7-04  [C0402_2]  103.15 71.73 180 top
C454  .1u-16vy5-04-o  [C0402_2]  161.65 71.12 270 top
C457  22u-6v3x5-08-o  [C0805_2]  72.11 70.99 270 top
C458  22u-6v3x5-08-o  [C0805_2]  74.14 70.99 270 top
C462  .01u-25vx7-04  [C0402_2]  92.43 70.76 180 top
C464  .1u-16vx7-04  [C0402_2]  149.07 70.74 180 top
C465  .01u-25vx7-04  [C0402_2]  103.15 70.59 180 top
C466  150p-25vx7-04-o  [C0402_2]  153.9 69.85 0 top
C467  1u-16vx7-06-o  [C0603_2]  188.57 69.72 0 top
C468  .1u-16vy5-04  [C0402_2]  11.99 69.27 270 top
C469  .1u-16vy5-04-o  [C0402_2]  164.95 68.96 90 top
C470  10u-16vx5-08-o  [C0805_2]  136.09 68.83 0 top
C471  .1u-25vx7-06  [C0603_2]  151.74 68.58 0 top
C472  .1u-16vx7-04  [C0402_2]  139.42 68.45 180 top
C473  .01u-25vx7-04  [C0402_2]  92.35 68.22 180 top
C474  .1u-16vy5-04-o  [C0402_2]  157.07 68.2 180 top
C475  .01u-25vx7-04  [C0402_2]  103.12 68.02 180 top
C476  1u-16vx5-04  [C0402_2]  144.63 67.82 90 top
C477  .1u-16vx7-04  [C0402_2]  141.6 67.69 270 top
C478  10u-16vx5-08  [C0805_2]  146.15 67.18 90 top
C479  10u-16vx5-08  [C0805_2]  148.18 67.18 90 top
C480  .1u-16vy5-04-o  [C0402_2]  177.65 67.18 180 top
C481  .01u-25vx7-04  [C0402_2]  92.35 67.08 180 top
C482  1u-16vx7-06  [C0603_2]  188.57 67.06 180 top
C483  10u-16vx5-08  [C0805_2]  136.09 66.9 0 top
C484  10u-16vx5-08  [C0805_2]  139.42 66.9 180 top
C485  .01u-25vx7-04  [C0402_2]  103.12 66.88 180 top
C486  10u-6v3x5-08-o  [C0805_2]  115.93 65.79 90 top
C487  10u-6v3x5-08  [C0805_2]  117.96 65.79 90 top
C488  10u-16vx5-08-o  [C0805_2]  136.09 64.97 0 top
C489  .1u-16vx7-04-o  [C0402_2]  14.45 60.58 0 top
C490  22u-6v3x5-08-o  [C0805_2]  42.01 63.88 270 top
C491  22u-6v3x5-08-o  [C0805_2]  44.04 63.88 270 top
C492  .1u-16vx7-04  [C0402_2]  142.85 63.75 180 top
C493  1u-16vx7-06-o  [C0603_2]  160.12 63.25 90 top
C494  .1u-16vy5-04  [C0402_2]  7.47 67.06 180 top
C496  .1u-16vx7-04-o  [C0402_2]  136.75 61.34 0 top
C497  .1u-16vx7-04  [C0402_2]  145.26 61.21 90 top
C498  1u-6v3x5-04  [C0402_2]  146.41 61.21 90 top
C499  .1u-16vx7-04  [C0402_2]  147.55 61.21 90 top
C500  47u-6v3x5-08  [C0805_2]  149.07 61.21 90 top
C501  47u-6v3x5-08  [C0805_2]  151.1 61.21 90 top
C504  .1u-16vx7-04  [C0402_2]  144.75 59.56 180 top
C505  .1u-16vy5-04-o  [C0402_2]  132.31 59.44 90 top
C506  .1u-16vx7-04  [C0402_2]  133.45 59.44 90 top
C509  .1u-16vx7-04-o  [C0402_2]  142.34 59.06 0 top
C510  1u-25vx5-06-o  [C0603_2]  162.53 59.06 90 top
C511  4.7u-25vx5-08-o  [C0805_2]  156.82 58.8 90 top
C512  10u-6v3x5-08  [C0805_2]  158.85 58.8 90 top
C513  10u-6v3x5-08  [C0805_2]  160.88 58.8 90 top
C514  .1u-16vx7-04  [C0402_2]  144.75 58.42 180 top
C515  .1u-16vx7-04  [C0402_2]  126.09 58.29 270 top
C516  .1u-16vx7-04-o  [C0402_2]  44.04 58.01 0 top
C517  1u-16vx7-06  [C0603_2]  122.78 57.66 90 top
C518  .1u-16vx7-04  [C0402_2]  93.93 57.51 270 top
C519  10u-6v3x5-08  [C0805_2]  95.45 57.51 90 top
C520  10u-6v3x5-08  [C0805_2]  97.49 57.51 90 top
C521  .1u-16vx7-04-o  [C0402_2]  141.83 56.26 90 top
C522  .01u-25vx7-04-o  [C0402_2]  152.76 56.13 90 top
C523  .01u-25vx7-04-o  [C0402_2]  130.58 54.74 0 top
C524  220p-50vx7-04-o  [C0402_2]  158.98 54.48 180 top
C525  .1u-16vx7-04  [C0402_2]  132.18 54.23 270 top
C526  10u-10vy5-08-o  [C0805_2]  176.16 54.14 270 top
C527  .1u-16vx7-04  [C0402_2]  10.87 53.82 0 top
C528  .1u-16vx7-04  [C0402_2]  138.28 53.85 270 top
C529  10p-04-o  [C0402_2]  195.43 53.47 270 top
C530  47p-04-o  [C0402_2]  39.22 52.71 0 top
C531  .22u-16vx5-04  [C0402_2]  143.36 51.82 90 top
C532  .1u-16vy5-04  [C0402_2]  162.15 51.82 90 top
C533  1u-16vx5-04-o  [C0402_2]  163.3 51.82 270 top
C534  .1u-25vx7-06  [C0603_2]  119.86 50.55 90 top
C535  .1u-16vx7-04  [C0402_2]  125.96 50.55 90 top
C536  .1u-16vy5-04-o  [C0402_2]  139.29 50.04 270 top
C537  1500p-50vx7-04  [C0402_2]  111.61 47.88 180 top
C538  10p-04-o  [C0402_2]  193.78 47.62 90 top
C539  4.7u-25vx5-08-o  [C0805_2]  143.97 46.86 270 top
C540  4.7u-25vx5-08-o  [C0805_2]  149.56 46.86 90 top
C545  10u-6v3x5-08-o  [C0805_2]  151.51 46.86 90 top
C546  10u-6v3x5-08-o  [C0805_2]  153.47 46.86 90 top
C547  10u-6v3x5-08  [C0805_2]  155.42 46.86 90 top
C548  .1u-16vx7-04-o  [C0402_2]  96.19 46.48 270 top
C549  .1u-16vx7-04-o  [C0402_2]  98.78 46.48 270 top
C550  1u-10vy5-06  [C0603_2]  161.77 45.21 0 top
C551  .01u-25vx7-04-o  [C0402_2]  146.53 44.58 180 top
C552  22u-6v3x5-08-o  [C0805_2]  36.19 44.55 90 top
C553  22u-6v3x5-08-o  [C0805_2]  38.13 44.55 90 top
C554  .1u-16vx7-04  [C0402_2]  135.76 44.45 0 top
C555  .01u-04-o  [C0402_2]  140.31 44.45 0 top
C556  .1u-16vx7-04-o  [C0402_2]  100.03 43.54 90 top
C557  10p-04-o  [C0402_2]  93.75 42.93 180 top
C558  10u-6v3x5-06  [C0603_2]  127.63 44.17 180 top
C559  10u-10vy5-08  [C0805_2]  114.3 42.01 270 top
C560  10p-04-o  [C0402_2]  82.75 41.96 0 top
C561  .1u-16vx7-04  [C0402_2]  19.79 41.91 180 top
C562  10p-04-o  [C0402_2]  93.75 41.78 180 top
C563  1u-10vy5-06  [C0603_2]  112.65 41.76 270 top
C564  .1u-16vy5-04  [C0402_2]  116.18 41.4 90 top
C565  .1u-16vy5-04  [C0402_2]  117.32 41.4 90 top
C566  .1u-16vy5-04  [C0402_2]  118.47 41.4 90 top
C567  .1u-16vy5-04  [C0402_2]  119.61 41.4 90 top
C568  10p-04-o  [C0402_2]  82.78 40.89 0 top
C569  .1u-16vx7-04  [C0402_2]  19.79 40.77 180 top
C570  .1u-16vx7-04-o  [C0402_2]  93.75 40.67 0 top
C571  100p-04-o  [C0402_2]  87.78 40.11 180 top
C572  .1u-16vx7-04  [C0402_2]  19.79 39.6 180 top
C573  .1u-16vy5-04  [C0402_2]  119.74 39.29 0 top
C574  100p-04-o  [C0402_2]  84.81 39.04 0 top
C575  .1u-16vy5-04  [C0402_2]  125.45 38.81 180 top
C576  .1u-16vx7-04-o  [C0402_2]  97.64 38.74 90 top
C577  470p-50vx7-04-o  [C0402_2]  104.88 38.61 180 top
C578  .1u-16vx7-04  [C0402_2]  19.79 38.46 180 top
C579  10u-6v3x5-08-o  [C0805_2]  99.29 38.23 90 top
C580  1u-25vx5-06  [C0603_2]  120.12 38.1 180 top
C581  .1u-16vx7-04  [C0402_2]  125.45 37.74 0 top
C582  4700p-25vx7-04  [C0402_2]  123.06 37.03 270 top
C583  470p-50vx7-04-o  [C0402_2]  104.88 36.96 180 top
C584  10p-04-o  [C0402_2]  59.23 36.45 270 top
C585  .1u-16vy5-04-o  [C0402_2]  119.99 34.49 0 top
C586  10p-04-o  [C0402_2]  104.88 34.42 180 top
C587  1u-16vx7-06  [C0603_2]  50.5 34.32 270 top
C588  15p-04  [C0402_2]  47.98 34.16 180 top
C589  10p-04-o  [C0402_2]  52.3 33.78 270 top
C590  .1u-16vy5-04-o  [C0402_2]  14.1 33.53 180 top
C591  .1u-16vy5-04-o  [C0402_2]  104.88 33.27 180 top
C592  15p-04  [C0402_2]  47.35 32.26 90 top
C593  1u-6v3x5-04-o  [C0402_2]  92.05 31.62 180 top
C594  10p-04-o  [C0402_2]  54.58 31.24 270 top
C595  .1u-16vx7-04  [C0402_2]  142.09 31.24 180 top
C596  .1u-16vx7-04  [C0402_2]  134.26 30.86 270 top
C597  .1u-16vx7-04  [C0402_2]  135.33 30.86 270 top
C598  .1u-16vx7-04  [C0402_2]  162.28 30.86 270 top
C599  .1u-16vx7-04  [C0402_2]  176.38 30.86 270 top
C600  .1u-16vx7-04  [C0402_2]  104.88 30.76 180 top
C601  .1u-16vy5-04-o  [C0402_2]  188.95 30.1 180 top
C602  .1u-16vx7-04  [C0402_2]  129.51 29.97 270 top
C603  2.2u-6v3x5-06-o  [C0603_2]  101.7 29.46 180 top
C604  .1u-16vx7-04  [C0402_2]  104.88 29.34 180 top
C605  10p-04-o  [C0402_2]  119.99 29.03 180 top
C606  10p-04-o  [C0402_2]  49.12 28.58 270 top
C607  .1u-16vx7-04  [C0402_2]  6.96 28.32 90 top
C608  10p-04-o  [C0402_2]  104.88 28.19 180 top
C609  .1u-16vx7-04  [C0402_2]  139.04 27.81 270 top
C610  1u-16vx7-06  [C0603_2]  115.57 26.64 270 top
C611  10p-04-o  [C0402_2]  110.03 26.37 270 top
C612  47p-04-o  [C0402_2]  112.24 26.37 270 top
C613  10p-04  [C0402_2]  106.83 26.34 270 top
C614  .1u-16vy5-04-o  [C0402_2]  191.11 26.16 0 top
C615  1u-10vy5-06  [C0603_2]  120.32 25.93 0 top
C616  .1u-16vy5-04-o  [C0402_2]  83.16 25.91 270 top
C617  .1u-16vy5-04-o  [C0402_2]  85.45 25.91 90 top
C618  .1u-16vy5-04-o  [C0402_2]  88.87 25.91 270 top
C619  .1u-16vy5-04-o  [C0402_2]  93.83 25.91 270 top
C620  .1u-16vy5-04-o  [C0402_2]  76.56 25.4 270 top
C621  .1u-16vy5-04  [C0402_2]  34.44 23.67 90 top
C622  10p-04-o  [C0402_2]  53.57 23.39 270 top
C623  .1u-16vy5-04  [C0402_2]  48.87 18.69 90 top
C624  1u-10vy5-06-o  [C0603_2]  53.44 16.64 90 top
C625  .1u-16vx7-04  [C0402_2]  86.08 16.15 0 top
C626  .1u-16vx7-04  [C0402_2]  88.19 16.15 0 top
C627  10p-04-o  [C0402_2]  81.51 16.13 0 top
C628  .1u-16vx7-04  [C0402_2]  83.13 15.9 90 top
C629  .1u-16vy5-04  [C0402_2]  12.34 15.49 0 top
C630  .01u-25vx7-04  [C0402_2]  89.76 14.6 270 top
C631  .01u-25vx7-04  [C0402_2]  90.91 14.6 270 top
C632  .1u-16vx7-04-o  [C0402_2]  96.6 14.3 180 top
C633  .1u-16vx7-04-o  [C0402_2]  96.6 13.16 180 top
C634  .1u-16vx7-04-o  [C0402_2]  53.14 12.27 270 top
C635  12p-04-o  [C0402_2]  70.74 11.33 0 top
C636  .1u-16vx7-04  [C0402_2]  94.51 9.96 180 top
C637  12p-04-o  [C0402_2]  70.74 10.19 0 top
C638  1u-10vy5-06  [C0603_2]  17.88 9.91 90 top
C639  12p-04-o  [C0402_2]  56.64 9.4 180 top
C640  12p-04-o  [C0402_2]  56.64 6.2 180 top
C641  10u-10vy5-08  [C0805_2]  53.19 6.48 180 top
C642  12p-04-o  [C0402_2]  70.71 5.97 0 top
C643  .1u-16vx7-04  [C0402_2]  56.64 5.13 180 top
C644  330p-50vx7-04  [C0402_2]  167.23 224.03 270 top
C645  10u-6v3x5-06  [C0603_2]  177.77 30.96 270 top
C646  330p-50vx7-04  [C0402_2]  45.82 26.67 0 top
CHOKE1  cmk-90-08-hdmi-o  [WCM2012F2S_1]  117.58 225.73 90 top
CHOKE2  cmk-90-08-hdmi-o  [WCM2012F2S_1]  119.35 225.73 90 top
CHOKE3  cmk-90-08-hdmi-o  [WCM2012F2S_1]  121.82 225.73 90 top
CHOKE4  cmk-90-08-hdmi-o  [WCM2012F2S_1]  123.6 225.73 90 top
CHOKE5  cmk-90-08-hdmi-o  [WCM2012F2S_1]  135.18 223.32 90 top
CHOKE6  cmk-90-08-hdmi-o  [WCM2012F2S_1]  136.96 223.32 90 top
CHOKE7  cmk-90-08-hdmi-o  [WCM2012F2S_1]  139.62 223.32 90 top
CHOKE8  cmk-90-08-hdmi-o  [WCM2012F2S_1]  141.4 223.32 90 top
CHOKE9  cmk-50-08-usb3.0-o  [WCM2012F2S_1]  98.35 220.37 90 top
CHOKE10  cmk-50-08-usb3.0-o  [WCM2012F2S_1]  100.13 220.37 90 top
CHOKE11  cmk-50-08-usb3.0-o  [WCM2012F2S_1]  94.08 220.34 90 top
CHOKE12  cmk-50-08-usb3.0-o  [WCM2012F2S_1]  95.86 220.34 90 top
CHOKE13  cmk-90-08-o  [WCM2012F2S_1]  89.97 218.57 90 top
CHOKE14  cmk-90-08-o  [WCM2012F2S_1]  91.74 218.57 90 top
CHOKE15  cmk-50-08-usb3.0-o  [WCM2012F2S_1]  16.23 40.97 180 top
CHOKE16  cmk-50-08-usb3.0-o  [WCM2012F2S_1]  16.23 39.19 180 top
CHOKE17  cmk-50-08-usb3.0-o  [WCM2012F2S_1]  16.23 36.96 180 top
CHOKE18  cmk-50-08-usb3.0-o  [WCM2012F2S_1]  16.23 35.18 180 top
CLR_CMOS  h3x1-r  [J3X1]  185.52 69.6 270 top
CMK1  cmk-90-08-o  [CMM21_R0402]  14.45 70.36 90 top
CMK2  cmk-90-08-o  [CMM21_1]  17.25 32.44 270 top
CMK3  cmk-90-08-o  [CMM21_1]  17.25 30.73 270 top
CODEC  alc662-vd0-grs  [LQFP48]  18.14 217.55 90 top
CPU1  skl_s_cpu_lga  [LGA1151-INTEL]  123.37 147.57 0 top
CPU_FAN  h4x1-por  [J4X1_WAFER]  192.38 106.05 270 top
D1  bat54a-s  [SOT23_2MM_2]  13.82 228.6 180 top
D2  bat54a-s  [SOT23_2MM_2]  126.47 227.33 90 top
D3  az5125-02s-s  [SOT23_3L]  41.76 222.5 90 top
D4  bat54a-s  [SOT23_2MM_2]  144.98 220.34 0 top
D5  az5125-02s-s  [SOT23_3L]  56.54 219.3 180 top
D6  az5125-02s-s  [SOT23_3L]  48.06 219.28 180 top
D7  az5123-01h  [SOD_523]  82.52 214.25 90 top
D8  az5123-01h  [SOD_523]  78.84 213.74 90 top
D9  az5123-01h  [SOD_523]  63.73 210.57 90 top
D10  az5123-01h  [SOD_523]  67.67 210.57 90 top
D11  az5125-02s-s  [SOT23_3L]  10.59 210.45 270 top
D12  az5125-01h-s  [SOD_523]  26.9 207.8 0 top
D13  bav99-s  [SOT23_3L]  10.7 204.4 90 top
D14  az5125-02s-s  [SOT23_3L]  6.12 196.52 180 top
D15  bat54c-s-o  [SOT23_3L]  5.18 147.32 90 top
D16  1n4148-s  [SOD_123_2]  185.01 109.22 180 top
D17  bat54c-s  [SOT23_3L]  192.25 68.07 0 top
D18  1n4148-s  [SOD_123_2]  176.25 48.9 90 top
D19  esd3v3u4ulc-o  [FPC_4P10_R_1]  12.45 40.34 270 top
D20  esd3v3u4ulc-o  [FPC_4P10_R_1]  12.45 36.07 90 top
D21  1n4148-s  [SOD_123_2]  188.95 26.8 270 top
D22  bat54c-s-o  [SOT23_3L]  73.63 14.99 180 top
D23  bav99-s-o  [SOT23_3L]  13.92 10.54 0 top
D24  bav99-s-o  [SOT23_3L]  20.29 10.54 180 top
D25  bat54c-s-o  [SOT23_3L]  189.84 47.12 0 top
DIMM1  ddr3-240p-bl  [DDR3_240P_2]  178.84 86.1 270 top
DIMM2  ddr3-240p-bl  [DDR3_240P_2]  178.84 96.28 270 top
EC1  100u-16de  [EC2D5_6D3_H11MM]  6.55 224.87 0 top
EC2  220u-16de  [EC2D5_6D3_H11MM]  105.36 221.31 0 top
EC3  100u-16de  [EC2D5_6D3_H11MM]  33.1 220.56 0 top
EC4  100u-16de  [EC2D5_6D3_H11MM]  6.58 217.17 0 top
EC5  100u-16de  [EC2D5_6D3_H11MM]  33.12 213.49 0 top
EC6  220u-16de  [EC2D5_6D3_H11MM]  81.08 208.81 0 top
EC7  270u-16d-os  [EC3D5_8_H11MM_1P]  115.29 202.44 0 top
EC8  270u-16d-os-o  [EC3D5_8_H11MM_1P]  133.07 202.44 0 top
EC9  270u-16d-os  [EC3D5_8_H11MM_1P]  148.31 202.31 0 top
EC10  470u-16de-o  [EC3D5_8_H11MM_1P]  28.3 198.12 0 top
EC11  1000u-6v3ld8h11e-o  [EC3D5_8_H11D5MM_1P]  28.3 189.23 0 top
EC12  560u-6v3ld6h8e  [EC2D5_6D3_H8MM]  140.69 179.45 0 top
EC13  560u-6v3ld6h8e  [EC2D5_6D3_H8MM]  117.65 179.32 0 top
EC14  560u-6v3ld6h8e  [EC2D5_6D3_H8MM]  125.45 179.32 0 top
EC15  560u-6v3ld6h8e  [EC2D5_6D3_H8MM]  133.07 179.32 0 top
EC16  560u-2v5lod6h5.9e  [EC200_260_SMD]  108.05 179.04 0 top
EC17  560u-6v3ld6h8e  [EC2D5_6D3_H8MM]  166.93 177.8 0 top
EC18  560u-6v3ld6h8e  [EC2D5_6D3_H8MM]  166.93 170.56 0 top
EC19  560u-6v3ld6h8e-o  [EC2D5_6D3_H8MM]  167.25 163.45 0 top
EC20  270u-16d-os  [EC3D5_8_H11MM_1P]  191.36 161.16 0 top
EC21  560u-6v3ld6h8e  [EC2D5_6D3_H8MM]  166.93 156.34 0 top
EC22  560u-6v3ld6h8e  [EC2D5_6D3_H8MM]  166.93 149.23 0 top
EC23  560u-6v3ld6h8e  [EC2D5_6D3_H8MM]  166.93 142.11 0 top
EC24  560u-6v3ld6h8e  [EC2D5_6D3_H8MM]  127.33 107.44 270 top
EC25  100u-16de  [EC2D5_6D3_H11MM]  185.01 104.39 0 top
EC26  100u-16de  [EC2D5_6D3_H11MM]  10.39 75.44 270 top
EC27  560u-6v3ld6h8e  [EC2D5_6D3_H9MM]  168.25 74.68 0 top
EC28  560u-6v3ld6h8e  [EC2D5_6D3_H9MM]  123.16 64.01 0 top
EC29  560u-6v3ld6h8e  [EC2D5_6D3_H9MM]  130.28 64.01 0 top
EC30  100u-16de  [EC2D5_6D3_H11MM]  183.11 61.72 0 top
EC31  220u-16de  [EC2D5_6D3_H11MM]  7.49 57.38 270 top
EC32  100u-16de-o  [EC2D5_6D3_H11MM]  148.31 55.5 0 top
EC33  470u-6v3d6h11e-o  [EC2D5_6D3_H12D5MM]  165.96 55.5 0 top
EC34  820u-2v5d6h8e  [EC2D5_6D3_H8MM]  96.57 52.48 0 top
EC35  470u-6v3d6h11e  [EC2D5_6D3_H12D5MM]  165.96 48.13 0 top
EC36  220u-16de  [EC2D5_6D3_H11MM]  14.96 25.78 270 top
F1  fuse-1.1a-18  [FUSE_SMD_1]  161.9 228.85 180 top
F2  fuse-1.1a-18  [FUSE_SMD_1]  128.12 220.47 90 top
F_AUDIO  h5x2-p-p8e  [J5X2_AUDIO_1]  5.82 205.11 270 top
F_PANEL  h7x2-bk-p10e  [J7X2_PANEL_10P]  18.14 5.84 0 top
F_USB1  h5x2-bk-p9e  [J5X2_USB_1394]  5.94 20.19 270 top
F_USB2  h5x1-y-p5e  [J5X1_CR]  4.93 70.99 270 top
FB1  fb-30-04-b-o  [FB0402_2]  178.66 230.2 90 top
FB2  fb-30-04-b-o  [FB0402_2]  178.66 227.66 90 top
FB3  fb-30-04-b-o  [FB0402_2]  178.66 225.22 90 top
H1  hole-a  [HOLE8_5]  36.17 233.68 0 top
H2  hole-a  [HOLE8_5]  193.65 210.82 0 top
H3  hole-a  [HOLE8_5]  36.17 78.74 0 top
H4  hole-a  [HOLE8_5]  193.65 78.74 0 top
H5  hole-a  [HOLE8_5]  36.17 6.35 0 top
H6  hole-a  [HOLE8_5]  193.65 6.35 0 top
HDMI1  hdmi-19p_hi-top  [HDMI_19P-F_SMD-HIGH-TOP_5]  149.71 238.56 180 top
HDMI2  hdmi-19p_hi-top  [HDMI_19P-F_SMD-HIGH-TOP_5]  124.6 238.56 180 top
L1  fb120  [FB0603_2]  42.39 226.06 0 top
L2  fb120  [FB0603_2]  37.95 222.38 270 top
L3  fb120  [FB0603_2]  59.97 219.89 90 top
L4  fb120  [FB0603_2]  51.49 219.86 90 top
L5  fb120  [FB0603_2]  53.11 219.86 90 top
L6  fb120  [FB0603_2]  44.55 219.84 90 top
L7  cmk-90-08-muti-taitech  [WCM2012F2S_1]  55.24 214.12 180 top
L8  cmk-90-08-muti-taitech  [WCM2012F2S_1]  55.24 212.12 180 top
L9  ind-10u-08  [L0805_2]  29.36 208.86 90 top
L10  fb-120-s08-5a  [FB0805_2]  121.64 205.99 180 top
L11  ind-4.7u-29x25x21  [CHOKE_NLC252018_SMD_2P]  57.28 196.52 270 top
L12  rck-0.5ud-o  [CHOKE_9D5X11_PT7MM_H_2]  180.95 193.68 270 top
L13  pind-0.3u-38a  [CHOKE_R30_PT6D3X1D4MM_1]  125.7 189.61 90 top
L14  pind-0.3u-38a  [CHOKE_R30_PT6D3X1D4MM_1]  143.23 189.61 90 top
L15  pind-0.47u-dip  [CHOKE_PT3D5X5D5MM]  107.49 187.35 0 top
L16  pind-0.3u-38a  [CHOKE_R30_PT6D3X1D4MM_1]  178.66 169.93 0 top
L17  pind-0.3u-38a  [CHOKE_R30_PT6D3X1D4MM_1]  178.66 151.89 0 top
L18  pind-0.3u-38a  [CHOKE_R30_PT6D3X1D4MM_1]  178.66 134.49 0 top
L19  pind-1.0u-d-smd  [CHOKE_PT5D45MM_SMD]  65.13 131.44 0 top
L20  fb-120-s08-5a  [FB0805_2]  58.5 115.67 90 top
L21  cmk-90-08-o  [CMM21_R0402]  45.69 109.73 0 top
L22  inc0809-1r0m-jy1w  [CHOKE_1R0M_PT6D6X4D8MM]  131.8 75.41 180 top
L23  inc0809-1r0m-jy1w  [CHOKE_1R0M_PT6D6X4D8MM]  106.45 54.05 180 top
L24  fb120  [FB0603_2]  119.99 35.69 180 top
L25  cmk-90-08-o  [WCM2012F2S_1]  15.6 18.54 0 top
L26  cmk-90-08-o  [WCM2012F2S_1]  15.6 16.76 0 top
LPC_DEBUG  h10x2-bk-p4e-o  [J10X2_JLPC]  82.37 21.64 180 top
M2_1  m2_2230_key e_h3.2  [CON75P_PT05_SMD_P24_31-LOTES]  37.19 116.97 180 top
M2_2  m2_2280_key b_h3.2  [CON75P_PT05_SMD_B-LOTES]  103.33 14.17 90 top
ME_DISABLE  h3x1-b-o  [J3X1]  5.94 112.14 270 top
ME_TEST  h3x2-b-o  [J3X2]  6.58 139.95 270 top
NOREF  -  []  225.78 310.64 0 top
NOREF#2  -  []  197.71 178.31 270 top
NOREF#3  -  []  82.77 17.07 0 top
NOREF#4  -  []  -25.58 138.05 270 top
NOREF#5  -  []  143.19 106.69 180 top
NOREF#6  -  []  107.3 304.8 0 top
NOREF#7  -  []  200 243.84 270 top
NOREF#8  -  []  104.64 108.18 270 top
NOREF#9  -  []  198.07 115.98 270 top
NOREF#10  -  [unnamed#2]  5.08 238.89 0 top
NOREF#11  -  []  125.82 5.74 0 top
NOREF#12  -  [unnamed#3]  61.57 53.72 0 top
NOREF#13  -  []  40.25 154.37 270 top
NOREF#14  -  []  286.12 -24.38 90 top
NOREF#15  -  []  200 243.84 270 top
NOREF#16  -  []  563.23 -677.26 90 top
NOREF#17  -  []  214.45 325.86 0 top
NOREF#18  -  [unnamed#2]  195.2 220.7 0 top
NOREF#19  -  [unnamed#2]  195.02 14.96 0 top
NOREF#20  -  []  99.53 4.58 180 bottom
NOREF#21  -  []  170.43 14.34 180 bottom
NOREF#22  -  [unnamed#2]  5.03 5.33 180 bottom
NOREF#23  -  []  165.14 8.19 180 bottom
NOREF#24  -  []  91.67 4.83 180 bottom
NOREF#25  -  []  82.99 6.15 180 bottom
NOREF#26  -  []  69.21 4.83 180 bottom
NOREF#27  -  [unnamed#2]  5.13 239.17 180 bottom
NOREF#28  -  [unnamed#2]  195.02 14.96 180 bottom
NOREF#29  -  []  -95.52 133.74 180 bottom
PCH1  spt_pch_dt  [BGA837-INTEL_1]  61.57 53.72 180 top
PCIE1X  pciex1-w  [PCIE_X1_36P_2]  37.74 186.74 0 top
PCIE16X  pciex16-gy  [PCIE_X16_164P_4]  17.43 186.75 0 top
PFB1  0-04-o  [FB0402_2]  184.1 234.31 0 top
PFB2  0-04-o  [FB0402_2]  194.41 232.23 180 top
PFB3  fb-60-04-b-o  [FB0402_2]  183.62 231.19 0 top
PFB4  fb-60-04-b-o  [FB0402_2]  195.99 229.16 90 top
PFB5  0-08  [FB0805_2]  156.51 227.91 0 top
PFB6  0-04-o  [FB0402_2]  184.12 223.01 90 top
PFB7  fb-120-s08-5a  [FB0805_2]  139.55 64.97 0 top
PFB8  fb-120-s08-5a  [FB0805_2]  128.5 59.06 180 top
PFB9  fb-120-s08-5a  [FB0805_2]  128.5 57.12 180 top
PFB10  fb600-06  [FB0603_2]  111.86 43.94 180 top
Q1  hbn2040s6r-s-o  [SOT363_6P]  11.79 236.6 0 top
Q2  hbn2040s6r-s  [SOT363_6P]  14.45 236.6 0 top
Q3  hbn2040s6r-s  [SOT363_6P]  16.99 236.6 0 top
Q4  hbn2040s6r-s  [SOT363_6P]  20.29 236.6 0 top
Q5  hbn2040s6r-s  [SOT363_6P]  23.09 236.6 0 top
Q6  pmbs3906-s  [SOT23_BCE_2]  39.17 217.98 90 top
Q7  pmbs3906-s  [SOT23_BCE_2]  39.17 214.26 90 top
Q8  pmbs3906-s  [SOT23_BCE_2]  39.17 210.52 90 top
Q9  mmbt3904-s  [SOT23_BCE_2]  125.45 207.01 180 top
Q10  pmbs3906-s  [SOT23_BCE_2]  39.17 206.93 90 top
Q11  nx3008nbkv-o  [SOT_563_6P_1]  155.8 199.9 90 top
Q13  mmbt3904-s-o  [SOT23_BCE_2]  6.41 130.4 90 top
Q14  mmbt3904-s  [SOT23_BCE_2]  6.4 126.75 90 top
Q15  mmbt3904-s  [SOT23_BCE_2]  50.14 126.37 180 top
Q16  mmbt3904-s  [SOT23_BCE_2]  53.82 126.37 180 top
Q17  mmbt3904-s  [SOT23_BCE_2]  6.4 123.11 90 top
Q18  mmbt3904-s  [SOT23_BCE_2]  6.4 119.46 90 top
Q19  mmbt3904-s-o  [SOT23_BCE_2]  191.15 118.17 270 top
Q20  mmbt3904-s-o  [SOT23_BCE_2]  187.22 118.13 270 top
Q21  mmbt3904-s  [SOT23_BCE_2]  5.99 106.1 180 top
Q22  btb772i3-d-o  [TO251_BCE_PT90_1]  179.3 69.6 0 top
Q23  sm2305psa-s  [SOT23_GDS_2]  167.49 68.96 270 top
Q24  mmbt3904-s  [SOT23_BCE_2]  161.26 66.68 0 top
